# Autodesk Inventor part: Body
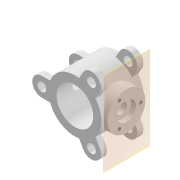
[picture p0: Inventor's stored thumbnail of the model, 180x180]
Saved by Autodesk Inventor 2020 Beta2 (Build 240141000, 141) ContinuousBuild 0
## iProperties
Created: 2019-03
Part Number: Body
Material: Generic
Document SubType Name: Modeling
Designer: LENOVO-CADCIM
Density: 1 g/cm^3
Appearance: Default
Author: LENOVO-CADCIM
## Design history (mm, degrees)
sketch "Sketch1"
  geometry: C1 r 140 at (0, 0); C2 r 97 at (0, 0); 1 further point
  constraints: 2 centre point, 2 coincident
  dimensions: "d0" = 194 diameter of C2; "d1" = 280 diameter of C1
extrude "Extrusion1" new body sketch "Sketch1" stored distance "d2" = 225; taper "d3" = 0 deg
sketch "Sketch2"
  geometry: L1 (0, 0)-(-428, 0); L2 (-130.767, 50)-(-175, 50); L3 (-130.767, -50)-(-175, -50); C1 r 23.5 at (-175, 0); A1 r 175 centre (0, 0) between (-175, 0) and (-175, 0); A2 r 140 centre (0, 0) between (-130.767, 50) and (-130.767, -50) reference; A3 r 50 centre (-175, 0) between (-175, 50) and (-175, -50); 1 further point
  constraints: 6 end point, 6 point on circle, 3 centre point, 3 horizontal, 2 tangent, 1 coincident, 1 point on line, 1 other
  dimensions: "d4" = 350 diameter of A1; "d5" = 50 radius of A3; "d6" = 47 diameter of C1
extrude "Extrusion2" join sketch "Sketch2" distance "d7" = 32; taper "d8" = 0 deg
pattern_circular "Circular Pattern1" dims angle "d10" = 360 deg
mirror "Mirror1"
workplane "Work Plane1"
sketch "Sketch3"
  geometry: C1 r 100 at (0, 0); 1 further point
  constraints: 1 centre point, 1 coincident
  dimensions: "d13" = 200 diameter of C1
extrude "Extrusion3" join sketch "Sketch3" stored distance "d14" = 32; taper "d15" = 0 deg
sketch "Sketch4" dims "d16" = 150
  geometry: L1 (0, 0)-(102, 0); 2 further points
  constraints: 2 end point, 1 coincident, 1 horizontal, 1 horizontal alignment, 1 point on line, 2 other
hole "Hole1" sketch "Sketch4" at (75, 0) diameter "d17" = 18.376; stored, may be unused: countersink angle "d21" = 90 deg, drill point angle "d23" = 118 deg; dims "d18" = 40, "d19" = 4, "d20" = 2, "d22" = 47.3
pattern_circular "Circular Pattern2" dims angle "d25" = 360 deg
sketch "Sketch5"
  geometry: C1 r 100 at (0, 0) reference; 2 further points
  constraints: 1 coincident
hole "Hole2" sketch "Sketch5" at (0, 0) diameter "d27" = 56; stored, may be unused: countersink angle "d31" = 90 deg, drill point angle "d33" = 118 deg; dims "d28" = 6, "d29" = 100, "d30" = 25, "d32" = 310
body "Solid1"
